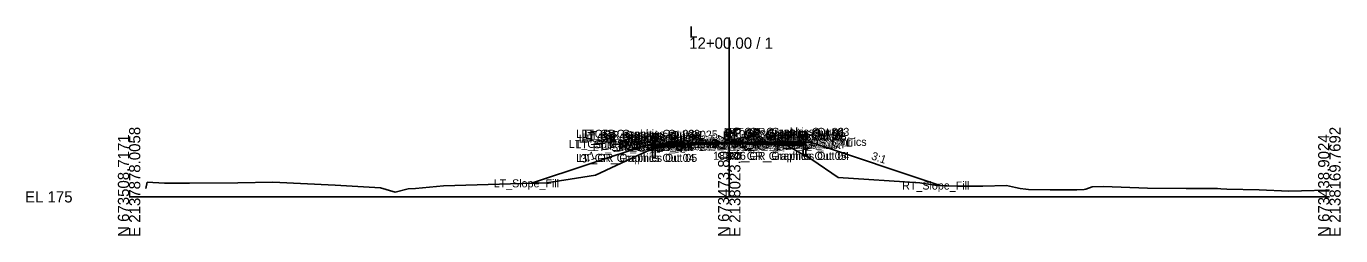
# Model space of a CAD drawing. Extents: x -26 to 5503, y -10 to 7033.
# Drawn here: x -25.7 to 302.8, y 2990.3 to 3042.6 of the extents above; entities that cross this region are included whole.
import ezdxf

# ---------------------------------------------------------------- set-up
doc = ezdxf.new("R2010")
doc.units = 0
for name, color, linetype in [('Default', 7, 'Continuous'), ('Exist CMT Pavement', 7, 'Continuous'), ('Exist Cross Section Cell', 7, 'Continuous'), ('Exist XS Center Line Elevation Label', 7, 'Continuous'), ('Exist XS Ground Line', 7, 'Continuous'), ('Prop CMT Guardrail Graphics', 7, 'Continuous'), ('Prop CMT Pvmt Course 1', 7, 'Continuous'), ('Prop CMT Pvmt Course 1 Wedge', 7, 'Continuous'), ('Prop CMT Pvmt Course 2', 7, 'Continuous'), ('Prop CMT Pvmt Course 2 Wedge', 7, 'Continuous'), ('Prop CMT Pvmt Course 3', 7, 'Continuous'), ('Prop CMT Pvmt Course 3 Wedge', 7, 'Continuous'), ('Prop CMT Pvmt Surface', 7, 'Continuous'), ('Prop CMT Pvmt Surface Shoulder', 7, 'Continuous'), ('Prop CMT Pvmt Wedge Surface 1', 7, 'Continuous'), ('Prop CMT Pvmt Wedge Surface 2', 7, 'Continuous'), ('Prop CMT Pvmt Wedge Surface 3', 7, 'Continuous'), ('Prop CMT Shld Paved Course 1', 7, 'Continuous'), ('Prop CMT Shld Paved Course 2', 7, 'Continuous'), ('Prop CMT Shld Paved Course 3', 7, 'Continuous'), ('Prop CMT Slope Grass', 7, 'Continuous'), ('Prop CMT Subgrade Earthwork', 7, 'Continuous'), ('Prop XS Earthwork Shape', 7, 'Continuous'), ('Prop XS EOT Tick Mark', 7, 'Continuous'), ('Prop XS SE Text', 7, 'Continuous'), ('Prop XS Side Slope Text', 7, 'Continuous'), ('Prop XS Wedging', 7, 'Continuous')]:
    doc.layers.add(name, color=color, linetype=linetype)

msp = doc.modelspace()

# ---------------------------------------------------------------- linework, layer by layer
at = {"layer": 'Exist CMT Pavement'}
for points in [[(150, 3013.26), (148.67, 3013.24), (144.01, 3013.16), (139.34, 3013.09), (138.01, 3013.07)], [(150, 3013.26), (151.33, 3013.24), (155.99, 3013.14), (160.66, 3013.05), (161.99, 3013.02)]]:
    msp.add_lwpolyline(points, dxfattribs=at)
at = {"layer": 'Exist Cross Section Cell'}
for p, q in [((150, 3000), (150, 3039.79)), ((0, 3000), (150, 3000)), ((150, 3000), (300, 3000))]:
    msp.add_line(p, q, dxfattribs=at)
at = {"layer": 'Exist XS Ground Line'}
for p, q in [((131.42, 3012.26), (135.68, 3012.82)), ((135.68, 3012.82), (137.01, 3013.01)), ((137.01, 3013.01), (137.56, 3013.06)), ((137.56, 3013.06), (150.1, 3013.26)), ((150.1, 3013.26), (161.97, 3013.02)), ((161.97, 3013.02), (164.73, 3012.65)), ((164.73, 3012.65), (170.63, 3009.29)), ((116.55, 3005.4), (126.88, 3010.21)), ((126.88, 3010.21), (131.42, 3012.26)), ((170.63, 3009.29), (177.24, 3004.84)), ((4.18, 3002.09), (4.49, 3003.68)), ((4.49, 3003.68), (8.89, 3003.4)), ((8.89, 3003.4), (15.06, 3003.43)), ((15.06, 3003.43), (27.21, 3003.52)), ((27.21, 3003.52), (35.92, 3003.68)), ((35.92, 3003.68), (51.52, 3002.89)), ((51.52, 3002.89), (62.86, 3002.23)), ((78.62, 3002.73), (98.14, 3003.3)), ((98.14, 3003.3), (104.33, 3003.5)), ((104.33, 3003.5), (110.24, 3004.45)), ((110.24, 3004.45), (116.55, 3005.4)), ((177.24, 3004.84), (197.68, 3003.49)), ((197.68, 3003.49), (201.86, 3002.85)), ((201.86, 3002.85), (207.15, 3002.67)), ((213.4, 3002.71), (219.34, 3002.83)), ((219.34, 3002.83), (221.58, 3002.32)), ((62.86, 3002.23), (66.48, 3001.18)), ((66.48, 3001.18), (69.78, 3002.01)), ((69.78, 3002.01), (71.55, 3002.06)), ((71.55, 3002.06), (78.62, 3002.73)), ((207.15, 3002.67), (213.4, 3002.71)), ((221.58, 3002.32), (222.71, 3002.06)), ((222.71, 3002.06), (224.16, 3001.94)), ((224.16, 3001.94), (224.81, 3001.84)), ((224.81, 3001.84), (230.25, 3001.72)), ((230.25, 3001.72), (236.86, 3001.75)), ((236.86, 3001.75), (238.75, 3001.86)), ((238.75, 3001.86), (239.14, 3001.93)), ((239.14, 3001.93), (240.72, 3002.53)), ((240.72, 3002.53), (243.59, 3002.55)), ((243.59, 3002.55), (254.54, 3002.14)), ((254.54, 3002.14), (264.18, 3002.11)), ((264.18, 3002.11), (272.01, 3002.06)), ((272.01, 3002.06), (272.88, 3002.02)), ((272.88, 3002.02), (274.37, 3001.92)), ((274.37, 3001.92), (282.46, 3001.75)), ((282.46, 3001.75), (289.91, 3001.44)), ((289.91, 3001.44), (293.03, 3001.53)), ((293.03, 3001.53), (299.42, 3001.68)), ((299.42, 3001.68), (300, 3001.68))]:
    msp.add_line(p, q, dxfattribs=at)
at = {"layer": 'Prop CMT Guardrail Graphics'}
for points in [[(169.14, 3016.23), (167.81, 3016.23), (167.54, 3015.94)], [(167.54, 3015.94), (167.81, 3015.65)], [(169.14, 3010.23), (169.14, 3016.23)], [(130.86, 3009.74), (130.86, 3015.74)], [(130.86, 3015.74), (132.19, 3015.74), (132.46, 3015.45)], [(132.46, 3014.87), (132.19, 3014.57), (131.53, 3014.57)], [(131.53, 3014.57), (131.53, 3009.74)], [(132.46, 3015.45), (132.19, 3015.16)], [(132.19, 3015.16), (132.46, 3014.87)], [(167.81, 3015.65), (167.54, 3015.36)], [(167.54, 3015.36), (167.81, 3015.07), (168.47, 3015.07)], [(168.47, 3015.07), (168.47, 3010.23)], [(131.53, 3009.74), (130.86, 3009.74)], [(168.47, 3010.23), (169.14, 3010.23)]]:
    msp.add_lwpolyline(points, dxfattribs=at)
at = {"layer": 'Prop CMT Pvmt Course 1'}
for points in [[(150, 3013.68), (138, 3013.38)], [(138, 3013.38), (138, 3013.13)], [(138, 3013.13), (138.01, 3013.13)], [(138.01, 3013.26), (150, 3013.56)], [(138.01, 3013.13), (138.01, 3013.26)], [(150, 3013.68), (162, 3013.72)], [(150, 3013.56), (150, 3013.68)], [(150, 3013.56), (150, 3013.68)], [(161.99, 3013.59), (150, 3013.56)], [(161.99, 3013.47), (161.99, 3013.59)], [(162, 3013.47), (161.99, 3013.47)], [(162, 3013.72), (162, 3013.47)]]:
    msp.add_lwpolyline(points, dxfattribs=at)
at = {"layer": 'Prop CMT Pvmt Course 1 Wedge'}
for points in [[(150, 3013.56), (138.01, 3013.26)], [(150, 3013.56), (161.99, 3013.59)]]:
    msp.add_lwpolyline(points, dxfattribs=at)
at = {"layer": 'Prop CMT Pvmt Course 2'}
for points in [[(138.01, 3013.13), (138, 3013.13)], [(138, 3013.13), (138, 3012.92)], [(138, 3012.92), (138.01, 3012.92)], [(138.01, 3012.92), (138.01, 3013.13)]]:
    msp.add_lwpolyline(points, dxfattribs=at)
at = {"layer": 'Prop CMT Pvmt Course 2 Wedge'}
for points in [[(150, 3013.43), (138.01, 3013.13)], [(150, 3013.43), (161.99, 3013.47)]]:
    msp.add_lwpolyline(points, dxfattribs=at)
at = {"layer": 'Prop CMT Pvmt Course 3'}
for points in [[(138.01, 3012.92), (138, 3012.92)], [(138, 3012.92), (138, 3012.59)], [(138.01, 3012.59), (138.01, 3012.92)], [(161.99, 3013.26), (162, 3013.26)], [(161.99, 3012.92), (161.99, 3013.26)], [(162, 3012.92), (161.99, 3012.92)], [(162, 3013.26), (162, 3012.92)], [(138, 3012.59), (138.01, 3012.59)]]:
    msp.add_lwpolyline(points, dxfattribs=at)
at = {"layer": 'Prop CMT Pvmt Course 3 Wedge'}
for points in [[(150, 3013.22), (138.01, 3012.92)], [(150, 3013.22), (161.99, 3013.26)]]:
    msp.add_lwpolyline(points, dxfattribs=at)
at = {"layer": 'Prop CMT Pvmt Surface'}
for points in [[(150, 3013.68), (138, 3013.38)], [(150, 3013.68), (162, 3013.72)]]:
    msp.add_lwpolyline(points, dxfattribs=at)
at = {"layer": 'Prop CMT Pvmt Surface Shoulder'}
for points in [[(138, 3013.38), (132.47, 3013.24)], [(162, 3013.72), (167.53, 3013.73)]]:
    msp.add_lwpolyline(points, dxfattribs=at)
at = {"layer": 'Prop CMT Pvmt Wedge Surface 1'}
for points in [[(138.01, 3013.38), (138, 3013.38)], [(150, 3013.56), (138.01, 3013.26)], [(138.01, 3013.26), (138.01, 3013.38)], [(150, 3013.56), (161.99, 3013.59)], [(161.99, 3013.59), (161.99, 3013.72)], [(161.99, 3013.72), (162, 3013.72)]]:
    msp.add_lwpolyline(points, dxfattribs=at)
at = {"layer": 'Prop CMT Pvmt Wedge Surface 2'}
for points in [[(150, 3013.43), (138.01, 3013.13), (138, 3013.13)], [(138, 3013.13), (138, 3013.38)], [(150, 3013.43), (161.99, 3013.47), (162, 3013.47)], [(162, 3013.47), (162, 3013.72)]]:
    msp.add_lwpolyline(points, dxfattribs=at)
at = {"layer": 'Prop CMT Pvmt Wedge Surface 3'}
for points in [[(138, 3012.92), (138, 3013.38)], [(150, 3013.22), (138.01, 3012.92), (138, 3012.92)], [(150, 3013.22), (161.99, 3013.26), (162, 3013.26)], [(162, 3013.26), (162, 3013.72)]]:
    msp.add_lwpolyline(points, dxfattribs=at)
at = {"layer": 'Prop CMT Shld Paved Course 1'}
for points in [[(138, 3013.38), (132.47, 3013.24), (132.22, 3012.99)], [(132.22, 3012.99), (138, 3013.13)], [(138, 3013.13), (138, 3013.38)], [(162, 3013.72), (167.53, 3013.73), (167.78, 3013.48)], [(162, 3013.47), (162, 3013.72)], [(167.78, 3013.48), (162, 3013.47)]]:
    msp.add_lwpolyline(points, dxfattribs=at)
at = {"layer": 'Prop CMT Shld Paved Course 2'}
for points in [[(138, 3013.13), (132.22, 3012.99), (132, 3012.77)], [(132, 3012.77), (138, 3012.92)], [(138, 3012.92), (138, 3013.13)], [(162, 3013.47), (167.78, 3013.48), (167.98, 3013.28)], [(162, 3013.26), (162, 3013.47)], [(167.98, 3013.28), (162, 3013.26)]]:
    msp.add_lwpolyline(points, dxfattribs=at)
at = {"layer": 'Prop CMT Shld Paved Course 3'}
for points in [[(132, 3012.77), (131.66, 3012.43)], [(138, 3012.92), (132, 3012.77)], [(132, 3012.77), (132, 3012.77)], [(138, 3012.59), (138, 3012.92)], [(162, 3013.26), (167.98, 3013.28)], [(162, 3012.92), (162, 3013.26)], [(168.32, 3012.94), (162, 3012.92)], [(167.98, 3013.28), (167.98, 3013.28)], [(167.98, 3013.28), (168.32, 3012.94)], [(131.66, 3012.43), (138, 3012.59)]]:
    msp.add_lwpolyline(points, dxfattribs=at)
at = {"layer": 'Prop CMT Slope Grass'}
for points in [[(129.46, 3013), (100.6, 3003.38)], [(132.46, 3013.24), (129.46, 3013)], [(132.47, 3013.24), (132.46, 3013.24)], [(167.53, 3013.73), (167.54, 3013.73)], [(167.54, 3013.73), (170.54, 3013.56)], [(170.54, 3013.56), (202.75, 3002.82)]]:
    msp.add_lwpolyline(points, dxfattribs=at)
at = {"layer": 'Prop CMT Subgrade Earthwork'}
for points in [[(131.66, 3012.43), (130.97, 3013.12)], [(138.01, 3012.59), (138.01, 3013.07)], [(161.99, 3012.92), (161.99, 3013.02)], [(161.99, 3012.92), (162, 3012.92)], [(162, 3012.92), (168.32, 3012.94)], [(168.32, 3012.94), (169.02, 3013.65)], [(138, 3012.59), (131.66, 3012.43)], [(138.01, 3012.59), (138, 3012.59)]]:
    msp.add_lwpolyline(points, dxfattribs=at)
at = {"layer": 'Prop XS Earthwork Shape'}
for points in [[(132.96, 3012.46), (131.66, 3012.43), (130.97, 3013.12), (129.46, 3013), (100.6, 3003.38), (104.33, 3003.5), (110.24, 3004.45), (116.55, 3005.4), (126.88, 3010.21), (131.42, 3012.26)], [(132.96, 3012.46), (135.68, 3012.82), (137.01, 3013.01), (137.56, 3013.06), (138.01, 3013.07), (138.01, 3012.59)], [(150, 3013.26), (151.33, 3013.24), (150.1, 3013.26)], [(161.99, 3013.02), (162.69, 3012.93), (161.99, 3012.92)], [(162.69, 3012.93), (168.32, 3012.94), (169.02, 3013.65), (170.54, 3013.56), (202.75, 3002.82), (201.86, 3002.85), (197.68, 3003.49), (177.24, 3004.84), (170.63, 3009.29), (164.73, 3012.65)]]:
    msp.add_lwpolyline(points, close=True, dxfattribs=at)
at = {"layer": 'Prop XS EOT Tick Mark'}
for points in [[(138, 3013.38), (138, 3014.38)], [(138, 3013.38), (138, 3014.38)], [(162, 3013.72), (162, 3014.72)], [(162, 3013.72), (162, 3014.72)]]:
    msp.add_lwpolyline(points, dxfattribs=at)
at = {"layer": 'Prop XS Wedging'}
for p, q in [((138, 3014.38), (138, 3011.14)), ((162, 3014.72), (162, 3011.38))]:
    msp.add_line(p, q, dxfattribs=at)

# ---------------------------------------------------------------- texts
at = {"layer": 'Default'}
for s, height, p in [('LT_GR_Graphics Out 03', 2, (111.76, 3014.74)), ('LT_GR_Graphics Out 02', 2, (113.09, 3014.74)), ('LT_GR_Graphics Out 09', 2, (113.09, 3014.16)), ('LT_GR_Graphics Out 08', 2, (113.36, 3013.87)), ('LT_GR_Graphics Out 01', 2, (113.93, 3014.45)), ('RT_GR_Graphics Out 08', 2, (148.39, 3014.36)), ('RT_GR_Graphics Out 02', 2, (148.66, 3015.23)), ('RT_GR_Graphics Out 09', 2, (148.66, 3014.65)), ('RT_GR_Graphics Out 07', 2, (148.66, 3014.07)), ('RT_GR_Graphics Out 01', 2, (148.95, 3014.94)), ('RT_GR_Graphics Out 06', 2, (149.28, 3014.07)), ('RT_GR_Graphics Out 03', 2, (149.99, 3015.23)), ('LT_GS_OS_GR_Face_Graphics', 2, (109.92, 3012.24)), ('LT_Sub_Trench_Out_DLT', 2, (111.54, 3012.12)), ('LT_GR_Graphics Out 06', 2, (112.38, 3013.57)), ('LT_GR_Graphics Out 07', 2, (113.09, 3013.57)), ('LT_Sub_Trench_Out', 2, (115.87, 3011.43)), ('LT_PS3_Shelf_Out', 2, (117.99, 3011.77)), ('LT_GS_OS_CTL', 2, (118.83, 3012)), ('LT_PS3_OEOP', 2, (122.24, 3011.77)), ('LT_PS2_OEOP', 2, (122.45, 3011.99)), ('LT_PV_Sub_Tie_Out', 2, (122.96, 3012.07)), ('LT_PS1_OEOP', 2, (123.28, 3012.24)), ('LT_PV1_OEEOP_Null', 2, (124.47, 3012.38)), ('LT_PV_EG_TestPt3', 2, (124.85, 3012.09)), ('LT_PV_OEEOP_EG', 2, (125.55, 3012.07)), ('LT_PV1_OEEOP_W', 2, (125.99, 3012.26)), ('LT_Sub_OEEOP', 2, (127.22, 3011.59)), ('LT_PV2_OEEOP', 2, (127.32, 3012.13)), ('LT_PV3_OEEOP', 2, (127.32, 3011.92)), ('LT_Sub_OEOT', 2, (128.08, 3011.59)), ('LT_PV2_OEOT', 2, (128.17, 3012.13)), ('LT_PV3_OEOT', 2, (128.17, 3011.92)), ('LT_PV1_OEOT', 2, (128.74, 3012.38)), ('LT_TM_OEOT', 2, (128.94, 3013.38)), ('LT_PV_EG_TestPt2', 2, (129.52, 3012.16)), ('LT_PV_EG_TestPt1', 2, (134.75, 3012.24)), ('RT_PV_EG_TestPt1', 2, (137.36, 3012.24)), ('PV_EPGL_EG', 2, (141.24, 3012.26)), ('RT_PV_EG_TestPt2', 2, (141.46, 3012.14)), ('PV2_PGL_W', 2, (142.02, 3012.43)), ('PV3_PGL_W', 2, (142.02, 3012.22)), ('PV1_PGL_W', 2, (142.58, 3012.56)), ('PV1_PGL', 2, (144.47, 3012.68)), ('RT_GS_OS_GR_Face_Graphics', 2, (144.95, 3012.73)), ('RT_PV_EG_TestPt3', 2, (146.12, 3012.05)), ('RT_PV_Sub_Tie_Out', 2, (146.89, 3012.02)), ('RT_PV1_OEEOP_Null', 2, (148.4, 3012.72)), ('RT_PV_OEEOP_EG', 2, (149.48, 3012.02)), ('RT_Sub_Trench_Out_DLT', 2, (149.54, 3012.65)), ('RT_PV1_OEEOP_W', 2, (149.93, 3012.59)), ('RT_Sub_OEEOP', 2, (151.16, 3011.92)), ('RT_PV2_OEEOP', 2, (151.25, 3012.47)), ('RT_PV3_OEEOP', 2, (151.25, 3012.26)), ('RT_Sub_OEOT', 2, (152.03, 3011.92)), ('RT_PV2_OEOT', 2, (152.13, 3012.47)), ('RT_PV3_OEOT', 2, (152.13, 3012.26)), ('RT_Sub_Trench_Out', 2, (152.47, 3011.94)), ('RT_PV1_OEOT', 2, (152.69, 3012.72)), ('RT_TM_OEOT', 2, (152.9, 3013.72)), ('RT_PS3_Shelf_Out', 2, (153.92, 3012.28)), ('RT_PS2_OEOP', 2, (157.97, 3012.48)), ('RT_PS3_OEOP', 2, (158.17, 3012.28)), ('RT_PS1_OEOP', 2, (158.28, 3012.73)), ('RT_GS_OS_CTL', 2, (159.86, 3012.56)), ('LT_GR_Graphics Out 04', 2, (111.76, 3008.74)), ('LT_GR_Graphics Out 05', 2, (112.42, 3008.74)), ('RT_GR_Graphics Out 05', 2, (149.32, 3009.23)), ('RT_GR_Graphics Out 04', 2, (149.99, 3009.23)), ('LT_Slope_Fill', 2, (91.12, 3002.38)), ('RT_Slope_Fill', 2, (193.22, 3001.82)), ('-', 0.0001, (0, 3000))]:
    msp.add_text(s, height=height, dxfattribs=at).set_placement(p)
at = {"layer": 'Exist Cross Section Cell'}
for s, p in [('L', (140, 3039.79)), ('12+00.00 / 1', (140, 3036.99)), ('EL 175', (-26, 2998.6))]:
    msp.add_text(s, height=2.8, dxfattribs=at).set_placement(p)
for s, p in [('E 2137878.0058', (2.8, 2990)), ('E 2138023.8875', (152.8, 2990)), ('E 2138169.7692', (302.8, 2990)), ('N 673508.7171', (0, 2990)), ('N 673473.8097', (150, 2990)), ('N 673438.9024', (300, 2990))]:
    msp.add_text(s, height=2.8, rotation=90, dxfattribs=at).set_placement(p)
at = {"layer": 'Exist XS Center Line Elevation Label'}
msp.add_text('188.26', height=2, dxfattribs=at).set_placement((145.97, 3009.26))
at = {"layer": 'Prop XS SE Text'}
for s, rotation, p in [('0.025', 1.4321, (140.48, 3014.44)), ('0.003', 0.1719, (152.51, 3014.69))]:
    msp.add_text(s, height=2, rotation=rotation, dxfattribs=at).set_placement(p)
at = {"layer": 'Prop XS Side Slope Text'}
for rotation, p in [(18.4349, (113.28, 3008.4)), (341.5651, (185.36, 3009.41))]:
    msp.add_text('3:1', height=2, rotation=rotation, dxfattribs=at).set_placement(p)

doc.saveas('drawing.dxf')
